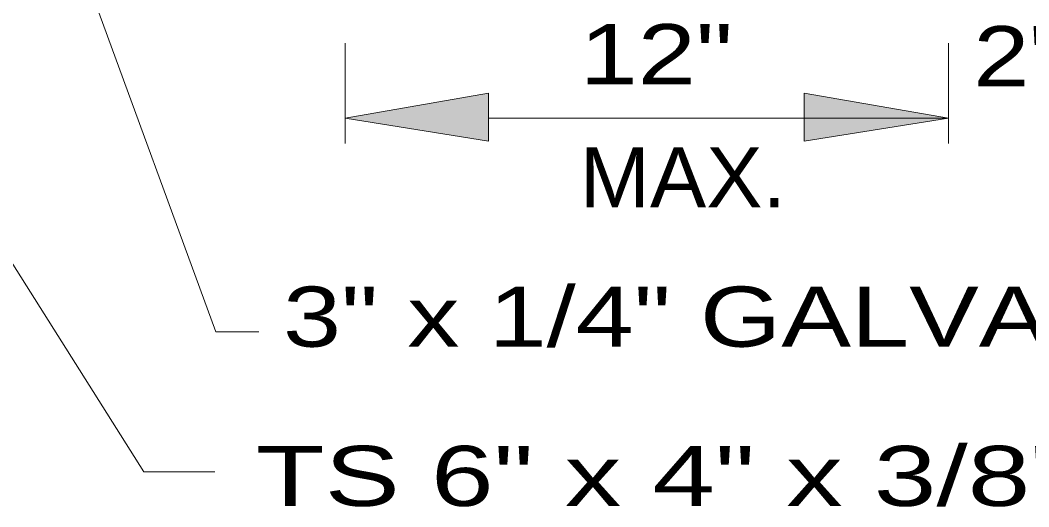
# Model space of a CAD drawing. Extents: x 5332.5 to 5339, y 1824.9 to 1835.1.
# Drawn here: x 5336.024 to 5337.03, y 1826.413 to 1826.899 of the extents above; entities that cross this region are included whole.
import ezdxf

# ---------------------------------------------------------------- set-up
doc = ezdxf.new("R2010")
doc.units = 0
doc.header["$LTSCALE"] = 0.024
doc.layers.add('10', color=7, linetype='Continuous', lineweight=13)
doc.layers.add('12', color=7, linetype='Continuous', lineweight=53)

msp = doc.modelspace()

# ---------------------------------------------------------------- hatches: boundary and pattern name
at = {"layer": '10'}
for points in [[(5336.491, 1826.778), (5336.491, 1826.826), (5336.348, 1826.801)], [(5336.491, 1826.778), (5336.491, 1826.826), (5336.348, 1826.801)], [(5336.491, 1826.778), (5336.491, 1826.826), (5336.348, 1826.801)], [(5336.491, 1826.778), (5336.491, 1826.826), (5336.348, 1826.801)], [(5336.491, 1826.778), (5336.491, 1826.826), (5336.348, 1826.801)], [(5336.491, 1826.778), (5336.491, 1826.826), (5336.348, 1826.801)], [(5336.491, 1826.778), (5336.491, 1826.826), (5336.348, 1826.801)], [(5336.491, 1826.778), (5336.491, 1826.826), (5336.348, 1826.801)], [(5336.491, 1826.778), (5336.491, 1826.826), (5336.348, 1826.801)], [(5336.491, 1826.778), (5336.491, 1826.826), (5336.348, 1826.801)], [(5336.491, 1826.778), (5336.491, 1826.826), (5336.348, 1826.801)], [(5336.806, 1826.778), (5336.806, 1826.826), (5336.95, 1826.801)], [(5336.806, 1826.778), (5336.806, 1826.826), (5336.95, 1826.801)], [(5336.806, 1826.778), (5336.806, 1826.826), (5336.95, 1826.801)], [(5336.806, 1826.778), (5336.806, 1826.826), (5336.95, 1826.801)], [(5336.806, 1826.778), (5336.806, 1826.826), (5336.95, 1826.801)], [(5336.806, 1826.778), (5336.806, 1826.826), (5336.95, 1826.801)], [(5336.806, 1826.778), (5336.806, 1826.826), (5336.95, 1826.801)], [(5336.806, 1826.778), (5336.806, 1826.826), (5336.95, 1826.801)], [(5336.806, 1826.778), (5336.806, 1826.826), (5336.95, 1826.801)], [(5336.806, 1826.778), (5336.806, 1826.826), (5336.95, 1826.801)], [(5336.806, 1826.778), (5336.806, 1826.826), (5336.95, 1826.801)]]:
    msp.add_hatch(color=256, dxfattribs=at).paths.add_polyline_path(points)

# ---------------------------------------------------------------- linework, layer by layer
for p, q in [((5336.348, 1826.876), (5336.348, 1826.776)), ((5336.348, 1826.876), (5336.348, 1826.776)), ((5336.348, 1826.876), (5336.348, 1826.776)), ((5336.348, 1826.876), (5336.348, 1826.776)), ((5336.348, 1826.876), (5336.348, 1826.776)), ((5336.348, 1826.876), (5336.348, 1826.776)), ((5336.348, 1826.876), (5336.348, 1826.776)), ((5336.348, 1826.876), (5336.348, 1826.776)), ((5336.348, 1826.876), (5336.348, 1826.776)), ((5336.348, 1826.876), (5336.348, 1826.776)), ((5336.348, 1826.876), (5336.348, 1826.776)), ((5336.95, 1826.876), (5336.95, 1826.776)), ((5336.95, 1826.876), (5336.95, 1826.776)), ((5336.95, 1826.876), (5336.95, 1826.776)), ((5336.95, 1826.876), (5336.95, 1826.776)), ((5336.95, 1826.876), (5336.95, 1826.776)), ((5336.95, 1826.876), (5336.95, 1826.776)), ((5336.95, 1826.876), (5336.95, 1826.776)), ((5336.95, 1826.876), (5336.95, 1826.776)), ((5336.95, 1826.876), (5336.95, 1826.776)), ((5336.95, 1826.876), (5336.95, 1826.776)), ((5336.95, 1826.876), (5336.95, 1826.776)), ((5336.491, 1826.801), (5336.95, 1826.801)), ((5336.491, 1826.801), (5336.95, 1826.801)), ((5336.491, 1826.801), (5336.95, 1826.801)), ((5336.491, 1826.801), (5336.95, 1826.801)), ((5336.491, 1826.801), (5336.95, 1826.801)), ((5336.491, 1826.801), (5336.95, 1826.801)), ((5336.491, 1826.801), (5336.95, 1826.801)), ((5336.491, 1826.801), (5336.95, 1826.801)), ((5336.491, 1826.801), (5336.95, 1826.801)), ((5336.491, 1826.801), (5336.95, 1826.801)), ((5336.491, 1826.801), (5336.95, 1826.801))]:
    msp.add_line(p, q, dxfattribs=at)
for points in [[(5336.095, 1826.927), (5336.219, 1826.588), (5336.262, 1826.588)], [(5335.979, 1826.714), (5336.147, 1826.448), (5336.218, 1826.448)], [(5335.979, 1826.714), (5336.147, 1826.448), (5336.218, 1826.448)], [(5335.979, 1826.714), (5336.147, 1826.448), (5336.218, 1826.448)], [(5335.979, 1826.714), (5336.147, 1826.448), (5336.218, 1826.448)], [(5335.979, 1826.714), (5336.147, 1826.448), (5336.218, 1826.448)], [(5335.979, 1826.714), (5336.147, 1826.448), (5336.218, 1826.448)], [(5335.979, 1826.714), (5336.147, 1826.448), (5336.218, 1826.448)], [(5335.979, 1826.714), (5336.147, 1826.448), (5336.218, 1826.448)], [(5335.979, 1826.714), (5336.147, 1826.448), (5336.218, 1826.448)], [(5335.979, 1826.714), (5336.147, 1826.448), (5336.218, 1826.448)], [(5335.979, 1826.714), (5336.147, 1826.448), (5336.218, 1826.448)]]:
    msp.add_lwpolyline(points, dxfattribs=at)
for points in [[(5336.491, 1826.778), (5336.491, 1826.826), (5336.348, 1826.801)], [(5336.491, 1826.778), (5336.491, 1826.826), (5336.348, 1826.801)], [(5336.491, 1826.778), (5336.491, 1826.826), (5336.348, 1826.801)], [(5336.491, 1826.778), (5336.491, 1826.826), (5336.348, 1826.801)], [(5336.491, 1826.778), (5336.491, 1826.826), (5336.348, 1826.801)], [(5336.491, 1826.778), (5336.491, 1826.826), (5336.348, 1826.801)], [(5336.491, 1826.778), (5336.491, 1826.826), (5336.348, 1826.801)], [(5336.491, 1826.778), (5336.491, 1826.826), (5336.348, 1826.801)], [(5336.491, 1826.778), (5336.491, 1826.826), (5336.348, 1826.801)], [(5336.491, 1826.778), (5336.491, 1826.826), (5336.348, 1826.801)], [(5336.491, 1826.778), (5336.491, 1826.826), (5336.348, 1826.801)], [(5336.806, 1826.778), (5336.806, 1826.826), (5336.95, 1826.801)], [(5336.806, 1826.778), (5336.806, 1826.826), (5336.95, 1826.801)], [(5336.806, 1826.778), (5336.806, 1826.826), (5336.95, 1826.801)], [(5336.806, 1826.778), (5336.806, 1826.826), (5336.95, 1826.801)], [(5336.806, 1826.778), (5336.806, 1826.826), (5336.95, 1826.801)], [(5336.806, 1826.778), (5336.806, 1826.826), (5336.95, 1826.801)], [(5336.806, 1826.778), (5336.806, 1826.826), (5336.95, 1826.801)], [(5336.806, 1826.778), (5336.806, 1826.826), (5336.95, 1826.801)], [(5336.806, 1826.778), (5336.806, 1826.826), (5336.95, 1826.801)], [(5336.806, 1826.778), (5336.806, 1826.826), (5336.95, 1826.801)], [(5336.806, 1826.778), (5336.806, 1826.826), (5336.95, 1826.801)]]:
    msp.add_lwpolyline(points, close=True, dxfattribs=at)

# ---------------------------------------------------------------- texts
at = {"layer": '12'}
for s, width, p in [('12"', 1.3, (5336.582, 1826.835)), ('2"', 1.25, (5336.975, 1826.833)), ('MAX.', 1.05, (5336.582, 1826.712)), ('3" x 1/4" GALVANIZED STEEL BAR', 1.3, (5336.286, 1826.573)), ('TS 6" x 4" x 3/8" GALVANIZED POST', 1.4, (5336.259, 1826.414))]:
    msp.add_text(s, height=0.06, dxfattribs=dict(at, width=width)).set_placement(p)

doc.saveas('drawing.dxf')
